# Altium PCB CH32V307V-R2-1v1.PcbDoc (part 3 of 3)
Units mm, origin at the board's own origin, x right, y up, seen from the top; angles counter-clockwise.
Board outline 80 x 115 mm, 2 copper layers (Top Layer, Bottom Layer); 122 components, 134 nets, 559 pads, 721 vias.
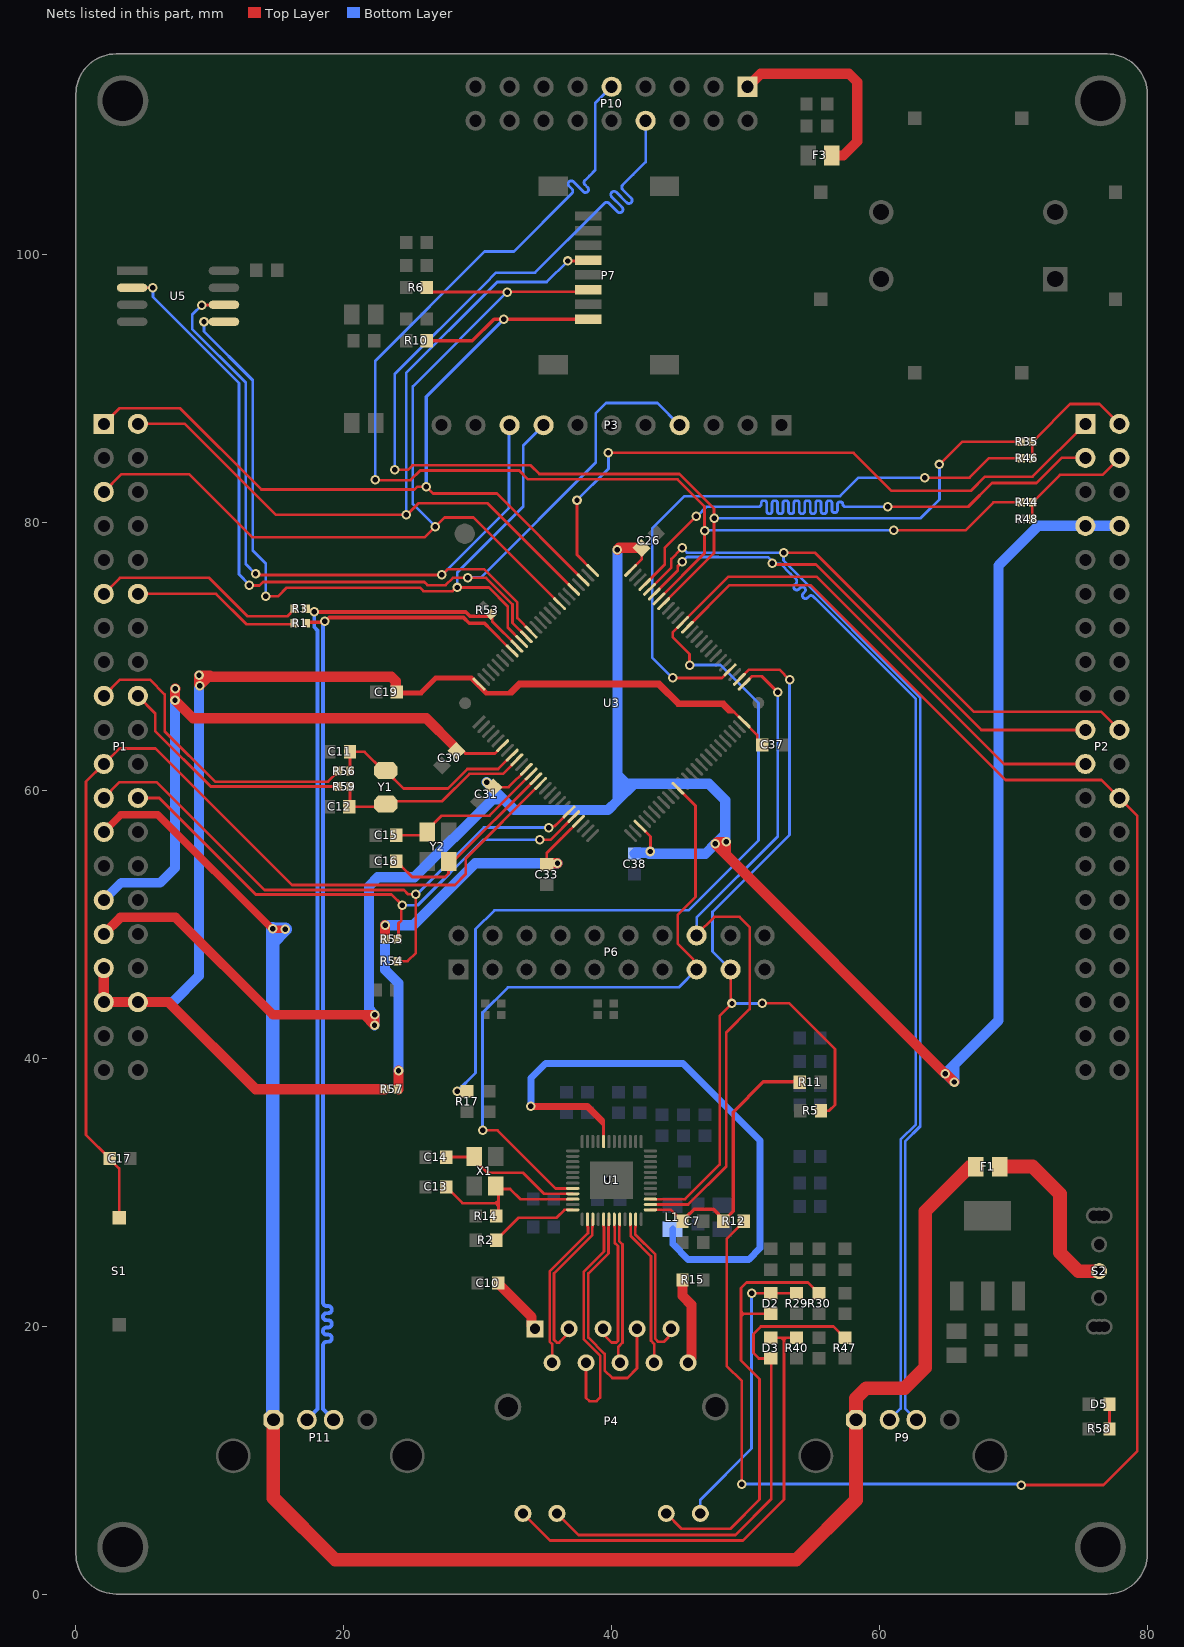
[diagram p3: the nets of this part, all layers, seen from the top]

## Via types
v1: diameter 0.711, hole 0.406, Top Layer to Bottom Layer, tented both sides, 507 vias
v2: diameter 0.61, hole 0.305, Top Layer to Bottom Layer, tented both sides, 214 vias

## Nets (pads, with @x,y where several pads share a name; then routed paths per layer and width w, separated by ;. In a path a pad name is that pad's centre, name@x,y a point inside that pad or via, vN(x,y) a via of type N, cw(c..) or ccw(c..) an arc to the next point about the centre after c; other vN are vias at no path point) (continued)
LED_green_n: D3.K P4.12 R47.1 | length 38.6
  Top Layer w0.203: P4.12@35.915,6.017 37.523,4.409 49.252,4.409 51.923,7.08 51.923,17.589 50.991,17.589 50.587,17.992 50.587,19.42 51.144,19.976 56.554,19.976 57.402,19.129 R47.1@57.427,19.129
LED_green_p: D3.A P4.11 R40.1 | length 36.1
  Top Layer w0.203: P4.11@33.375,6.017 35.395,3.997 49.814,3.997 52.873,7.056 52.873,18.932 ; D3.A@51.886,19.129 52.676,19.129 ; R40.1@53.817,19.129 53.027,19.129 ; 52.676,19.129 52.873,19.129 ; 52.676,19.129 52.873,18.932 ; 52.873,18.932 52.873,18.975 ; 52.873,18.975 52.873,19.129 ; 52.873,18.975 53.027,19.129 ; 52.873,19.129 53.027,19.129
LED_yellow_n: D2.K P4.13 R30.1 | length 33.9
  Top Layer w0.203: P4.13@44.085,6.017 45.228,4.875 48.869,4.875 51.049,7.055 51.049,16.059 49.658,17.451 49.658,20.716 ; D2.K@51.886,20.921 49.863,20.921 ; R30.1@55.495,22.461 55.47,22.461 54.67,23.261 50.079,23.261 49.658,22.84 49.658,21.127 ; 49.658,20.716 49.658,20.921 ; 49.658,20.716 49.863,20.921 ; 49.658,20.921 49.658,21.127 ; 49.658,20.921 49.863,20.921 ; 49.658,21.127 49.863,20.921
LED_yellow_p: D2.A P4.14 R29.2 | length 21.4
  Top Layer w0.203: v1(50.453,22.449) 51.392,22.449 51.404,22.461 R29.2@53.817,22.461
  Bottom Layer w0.203: P4.14@46.625,6.017 46.625,7.04 50.453,10.867 v1(50.453,22.449)
MAC_125M: P6.15 U1.44 U3.36 | length 49.8
  Top Layer w0.203: v1(30.368,34.627) 31.479,34.627 35.82,30.286 U1.44@37.1,30.286 ; U3.36@44.95,60.168 46.258,58.859 46.258,52.043 44.942,50.726 44.942,48.551 46.102,47.391 46.102,46.883 P6.15@46.35,46.634
  Bottom Layer w0.203: v1(30.368,34.627) 30.368,43.406 32.262,45.3 45.016,45.3 P6.15@46.35,46.634
MDI0_n: P4.3 U1.3 | length 12
  Top Layer w0.203: P4.3@36.823,19.807 36.823,19.519 36.075,18.771 35.925,18.771 35.793,18.903 35.704,18.992 35.704,23.949 38.565,26.811 38.565,27.411 38.597,27.442 38.597,27.983 U1.3@38.6,27.986
MDI0_p: P4.2 U1.2 | length 12
  Top Layer w0.203: P4.2@35.553,17.267 35.559,17.273 35.559,18.67 35.373,18.856 35.373,24.086 38.235,26.948 38.235,27.411 38.203,27.442 38.203,27.983 U1.2@38.2,27.986
MDI1_n: P4.7 U1.6 | length 18.3
  Top Layer w0.203: U1.6@39.8,27.986 39.797,27.983 39.797,27.442 39.765,27.411 39.765,25.436 38.26,23.931 38.26,19.152 39.479,17.932 39.479,16.701 40.052,16.129 41.173,16.129 41.903,16.859 P4.7@41.903,19.807
MDI1_p: P4.4 U1.5 | length 18.3
  Top Layer w0.203: P4.4@38.093,17.267 38.093,14.645 38.336,14.402 38.87,14.402 39.149,14.681 39.149,17.796 37.93,19.015 37.93,24.068 39.435,25.573 39.435,27.411 39.403,27.442 39.403,27.983 U1.5@39.4,27.986
MDI2_n: P4.6 U1.8 | length 11
  Top Layer w0.203: U1.8@40.6,27.986 40.597,27.983 40.597,27.442 40.565,27.411 40.565,26.356 40.813,26.108 40.813,18.768 40.499,18.454 40.499,17.402 P4.6@40.633,17.267
MDI2_p: P4.5 U1.7 | length 11
  Top Layer w0.203: P4.5@39.363,19.807 39.567,19.603 39.567,19.204 39.989,18.782 40.36,18.782 40.483,18.905 40.483,25.971 40.235,26.219 40.235,27.411 40.203,27.442 40.203,27.983 U1.7@40.2,27.986
MDI3_n: P4.9 U1.11 | length 11.5
  Top Layer w0.203: U1.11@41.8,27.986 41.797,27.983 41.797,27.442 41.765,27.411 41.765,26.852 43.264,25.353 43.264,19.052 43.48,18.836 43.902,18.836 44.239,19.173 44.239,19.603 P4.9@44.443,19.807
MDI3_p: P4.8 U1.10 | length 11.5
  Top Layer w0.203: U1.10@41.4,27.986 41.403,27.983 41.403,27.442 41.435,27.411 41.435,26.715 42.934,25.216 42.934,18.915 43.179,18.67 43.179,17.273 P4.8@43.173,17.267
NetC10_1: C10.1 P4.1 | length 4.5
  Top Layer w0.762: C10.1@31.526,23.212 31.526,23.187 34.029,20.684 34.029,20.061 P4.1@34.283,19.807
NetD5_K: D5.K R58.2 | length 1.8
  Top Layer w0.254: R58.2@77.178,12.329 D5.K@77.178,14.168
NetF1_2: F1.2 S2.1 | length 13.2
  Top Layer w1.016: F1.2@68.971,31.92 71.435,31.92 73.485,29.87 73.485,25.486 74.865,24.106 S2.1@76.403,24.106
NetF3_1: F3.1 P10.1 | length 15.6
  Top Layer w0.762: P10.1@50.16,112.547 51.125,113.512 57.724,113.512 58.335,112.901 58.335,108.457 57.297,107.419 F3.1@56.447,107.419
NetP2_2: P2.2 R35.1 R46.1 | length 9.5
  Top Layer w0.203: R46.1@71.416,84.811 R35.1@71.416,86.037 71.416,86.062 71.615,86.26 71.64,86.26 74.243,88.864 76.435,88.864 P2.2@77.919,87.38
NetP2_4: P2.4 R44.1 R48.1 | length 9.1
  Top Layer w0.203: R48.1@71.416,80.265 R44.1@71.416,81.518 71.416,81.543 71.615,81.741 71.64,81.741 73.468,83.569 76.648,83.569 P2.4@77.919,84.84
NetP4_10: P4.10 R15.1 | length 6.6
  Top Layer w0.762: R15.1@45.292,23.455 45.292,22.268 45.959,21.602 45.959,17.651 45.713,17.405 P4.10@45.713,17.267
NRST: C17.2 P1.21 S1.2 U3.14 | length 76.6
  Top Layer w0.203: S1.2@3.233,28.106 3.233,31.77 2.515,32.488 C17.2@2.515,32.513 2.515,32.538 0.762,34.291 0.762,60.661 P1.21@2.081,61.98 3.242,63.141 5.941,63.141 16.145,52.937 28.301,52.937 29.112,53.748 29.112,54.937 U3.14@34.697,60.522
PB6: P1.11 R3.2 | length 16.2
  Top Layer w0.203: P1.11@2.081,74.68 3.277,75.876 9.959,75.876 12.823,73.012 15.787,73.012 R3.2@16.336,73.562
PB7: P1.12 R1.2 | length 12.7
  Top Layer w0.203: P1.12@4.621,74.68 10.469,74.68 12.737,72.413 R1.2@16.336,72.413
PC14: P1.17 R56.2 | length 23.2
  Top Layer w0.203: P1.17@2.081,67.06 3.299,68.278 5.527,68.278 6.628,67.177 6.628,64.424 10.395,60.657 18.823,60.657 19.394,61.228 19.419,61.228 19.618,61.427 R56.2@19.618,61.452
PC15: P1.18 R59.2 | length 18.6
  Top Layer w0.203: P1.18@4.621,67.06 5.917,65.765 5.917,64.447 10.071,60.293 R59.2@19.618,60.293
PHY2_int: P2.21 R17.2 U3.64 | length 95.5
  Top Layer w0.203: v1(28.473,37.541) 28.73,37.541 28.847,37.425 29.205,37.783 R17.2@29.205,37.589 ; v1(45.822,69.367) 45.822,70.191 44.562,71.451 44.562,71.801 U3.64@45.303,72.542 48.729,75.968 55.306,75.968 69.294,61.98 P2.21@75.379,61.98
  Bottom Layer w0.203: v1(28.473,37.541) 29.837,38.905 29.837,49.643 31.246,51.052 45.734,51.052 50.961,56.279 50.961,66.533 48.127,69.367 v1(45.822,69.367)
PHY2_reset: P2.24 R12.2 U3.63 | length 140.7
  Top Layer w0.203: U3.63@45.657,72.189 48.801,75.333 54.855,75.333 69.41,60.777 76.582,60.777 P2.24@77.919,59.44 79.243,58.117 79.243,10.651 76.725,8.134 v1(70.582,8.134) ; v1(49.721,8.213) 49.721,15.908 48.592,17.038 48.592,26.524 49.875,27.808 R12.2@49.875,27.833
  Bottom Layer w0.203: v1(49.721,8.213) 70.502,8.213 v1(70.582,8.134)
PHYRSTB: C7.2 R11.1 R12.1 U1.13 | length 20.8
  Top Layer w0.178: U1.13@42.9,28.686 44.439,28.686 44.891,28.234 44.916,28.234 C7.2@45.292,27.858
  Top Layer w0.254: C7.2@45.292,27.858 45.63,28.196 46.173,28.738 47.608,28.738 48.424,27.921 48.424,27.946 48.673,28.196 48.698,28.196 49.08,28.577 49.08,35.989 51.333,38.242 54.035,38.242 R11.1@54.061,38.216
PVIN: F1.1 P1.25 P9.1 P11.1 | length 140.2
  Top Layer w0.559: P1.25@2.081,56.9 3.366,58.185 6.121,58.185 14.644,49.663 v1(14.685,49.663) 14.697,49.651 15.618,49.651 v1(15.629,49.639)
  Top Layer w1.016: P11.1@14.747,13.012 14.747,7.174 19.365,2.556 53.795,2.556 58.253,7.014 P9.1@58.253,13.012 58.253,14.614 59.015,15.377 61.887,15.377 63.42,16.91 63.42,28.58 66.743,31.903 F1.1@67.191,31.903
  Bottom Layer w1.016: P11.1@14.747,13.012 14.685,13.074 14.685,48.695 ; 14.685,48.695 v1(15.629,49.639) 14.709,49.639 v1(14.685,49.663) 14.685,48.695
REGOUT: L1.1 U1.32 | length 48.2
  Top Layer w0.203: 38.898,35.489 39.397,34.991 39.397,33.79 U1.32@39.4,33.786 39.4,35.21 ; 39.224,35.534 39.4,35.357 39.4,35.21 ; 39.243,35.367 39.4,35.21
  Top Layer w0.508: v1(33.978,36.408) 38.201,36.408 39.243,35.367
  Bottom Layer w0.508: v1(33.978,36.408) 33.978,38.523 35.077,39.622 45.322,39.622 51.088,33.857 51.088,25.824 50.243,24.98 45.715,24.98 44.571,26.123 L1.1@44.571,27.252
RGMII_MDC: P6.16 U1.14 U3.51 | length 54.2
  Top Layer w0.203: U1.14@42.9,29.086 45.718,29.086 48.561,31.929 48.561,41.939 50.31,43.689 50.31,49.797 49.545,50.562 47.68,50.562 46.35,49.232 P6.16@46.35,49.174 ; U3.51@49.899,67.946 49.906,67.946 50.49,68.53 51.21,68.53 v1(52.407,67.334)
  Bottom Layer w0.203: P6.16@46.35,49.174 46.35,50.515 52.407,56.572 v1(52.407,67.334)
RGMII_MDIO: P6.17 R5.2 U1.15 U3.52 | length 64.7
  Top Layer w0.203: U1.15@42.9,29.486 45.488,29.486 48.066,32.064 48.066,43.173 v1(48.989,44.096) 48.89,44.195 P6.17@48.89,46.634 ; U3.52@49.546,68.3 50.271,69.025 52.526,69.025 v1(53.288,68.263) ; v1(51.255,44.122) 53.243,44.122 56.682,40.684 56.682,36.527 56.241,36.086 R5.2@55.635,36.086
  Bottom Layer w0.203: P6.17@48.89,46.634 47.54,47.985 47.54,50.935 53.288,56.684 v1(53.288,68.263) ; v1(48.989,44.096) v1@51.255,44.096
RSET: R2.1 U1.48 | length 6.7
  Top Layer w0.203: R2.1@31.389,26.416 31.389,26.441 33.043,28.094 35.877,28.094 36.469,28.686 U1.48@37.1,28.686
SDIO_CLK: P1.2 P7.5 U3.80 | length 66.1
  Top Layer w0.203: P1.2@4.621,87.38 8.131,87.38 14.917,80.594 v1(24.663,80.594) 24.74,80.594 25.593,81.447 30.741,81.447 U3.80@37.172,75.017 ; v1(36.731,99.538) 38.231,99.538 38.272,99.579 P7.5@38.25,99.601
  Bottom Layer w0.203: v1(24.663,80.594) 24.663,91.041 24.663,91.16 30.901,97.398 31.464,97.961 35.154,97.961 v1(36.731,99.538)
SDIO_CMD: P1.5 P7.3 R6.1 U3.83 | length 73.2
  Top Layer w0.203: P1.5@2.081,82.3 3.398,83.617 8.453,83.617 13.172,78.899 26.043,78.899 v1(26.848,79.704) 27.524,80.381 29.687,80.381 U3.83@36.111,73.957 ; R6.1@26.192,97.549 26.524,97.217 v1(32.196,97.217) 32.228,97.249 38.098,97.249 P7.3@38.25,97.401
  Bottom Layer w0.203: v1(26.848,79.704) 25.158,81.393 25.158,90.178 v1(32.196,97.217)
SDIO_D2: P1.1 P7.1 R10.1 U3.78 | length 74.2
  Top Layer w0.203: P1.1@2.081,87.38 3.245,88.544 7.779,88.544 13.848,82.475 25.277,82.475 25.478,82.677 v1(26.162,82.677) 26.668,82.171 31.432,82.171 U3.78@37.87,75.733
  Top Layer w0.254: R10.1@26.192,93.583 29.602,93.583 31.219,95.201 36.775,95.201 ; v1(31.954,95.195) 36.769,95.195 36.775,95.201 ; P7.1@38.25,95.201 36.775,95.201
  Bottom Layer w0.254: v1(26.162,82.677) 26.162,89.404 v1(31.954,95.195)
SPI3_MISO: P3.4 U3.90 U5.2 | length 74.6
  Top Layer w0.203: U5.2@4.196,97.541 v1@5.751,97.542 ; v1(12.938,75.311) 13.709,75.311 13.963,75.566 26.013,75.566 26.247,75.331 27.603,75.331 28.149,75.878 v1(29.27,75.878) 30.626,75.878 32.603,73.901 32.603,72.515 U3.90@33.636,71.482
  Bottom Layer w0.203: v1(5.752,97.543) 5.752,96.856 12.173,90.435 12.173,76.148 12.938,75.383 v1(12.938,75.311) ; v1(29.27,75.878) 29.289,75.897 30.233,75.897 38.811,84.474 38.811,88.157 39.586,88.933 43.422,88.933 P3.4@45.08,87.274
SPI3_MOSI: P3.8 U3.91 U5.5 | length 60.9
  Top Layer w0.203: v1(9.564,95.017) 9.572,95.009 11.047,95.009 U5.5@11.054,95.001 ; v1(14.173,74.498) 15.097,74.498 15.743,75.144 25.692,75.144 25.952,74.884 28.13,74.884 28.405,75.159 30.842,75.159 32.247,73.754 32.247,72.164 U3.91@33.282,71.128
  Bottom Layer w0.203: v1(9.564,95.017) 9.564,94.27 13.204,90.631 13.204,77.929 14.173,76.96 v1(14.173,74.498) ; v1(28.473,75.159) 28.473,76.272 33.4,81.199 33.4,85.755 P3.8@34.92,87.274
SPI3_SCK: P3.9 U3.89 U5.6 | length 60.6
  Top Layer w0.203: v1(9.409,96.247) 9.421,96.259 11.042,96.259 U5.6@11.054,96.271 ; v1(13.411,76.175) 13.487,76.098 v1(27.33,76.098) ; v1@27.357,76.125 27.745,76.513 30.494,76.513 32.958,74.049 32.958,72.867 U3.89@33.99,71.835
  Bottom Layer w0.203: v1(9.409,96.247) 8.683,95.521 8.683,94.453 12.681,90.454 12.681,76.905 v1(13.411,76.175) ; v1(27.33,76.098) 32.339,81.107 32.339,87.234 P3.9@32.38,87.274
SWDCK: P2.1 U3.76 | length 49.3
  Top Layer w0.203: v1(37.416,81.681) 37.416,77.601 U3.76@38.586,76.431 ; v1(39.762,85.215) 58.055,85.215 60.892,82.378 66.82,82.378 67.871,83.429 71.428,83.429 P2.1@75.379,87.38
  Bottom Layer w0.203: v1@37.275,81.539 39.762,84.026 v1(39.762,85.215)
SWDIO: P2.3 U3.72 | length 49.3
  Top Layer w0.203: U3.72@42.475,75.371 43.962,76.858 43.962,78.12 v1(46.305,80.464) ; v1(60.634,81.185) 66.631,81.185 68.398,82.952 71.714,82.952 73.602,84.84 P2.3@75.379,84.84
  Bottom Layer w0.203: v1(46.305,80.464) 46.367,80.464 47.088,81.185 50.887,81.185 50.989,81.185 ccw(c50.989,81.368) 51.172,81.368 51.172,81.461 cw(c51.355,81.461) 51.355,81.644 51.395,81.644 cw(c51.395,81.461) 51.578,81.461 51.578,80.849 ccw(c51.761,80.849) 51.761,80.666 51.802,80.666 ccw(c51.802,80.849) 51.985,80.849 51.985,81.461 cw(c52.167,81.461) 52.167,81.644 52.208,81.644 cw(c52.208,81.461) 52.391,81.461 52.391,80.849 ccw(c52.574,80.849) 52.574,80.666 52.615,80.666 ccw(c52.615,80.849) 52.797,80.849 52.797,81.461 cw(c52.98,81.461) 52.98,81.644 53.021,81.644 cw(c53.021,81.461) 53.204,81.461 53.204,80.849 ccw(c53.387,80.849) 53.387,80.666 53.427,80.666 ccw(c53.427,80.849) 53.61,80.849 53.61,81.461 cw(c53.793,81.461) 53.793,81.644 53.834,81.644 cw(c53.834,81.461) 54.017,81.461 54.017,80.849 ccw(c54.199,80.849) 54.199,80.666 54.24,80.666 ccw(c54.24,80.849) 54.423,80.849 54.423,81.461 cw(c54.606,81.461) 54.606,81.644 54.647,81.644 cw(c54.647,81.461) 54.829,81.461 54.829,80.849 ccw(c55.012,80.849) 55.012,80.666 55.053,80.666 ccw(c55.053,80.849) 55.236,80.849 55.236,81.461 cw(c55.419,81.461) 55.419,81.644 55.459,81.644 cw(c55.459,81.461) 55.642,81.461 55.642,80.849 ccw(c55.825,80.849) 55.825,80.666 55.866,80.666 ccw(c55.866,80.849) 56.049,80.849 56.049,81.461 cw(c56.231,81.461) 56.231,81.644 56.272,81.644 cw(c56.272,81.461) 56.455,81.461 56.455,80.932 ccw(c56.638,80.932) 56.638,80.749 56.679,80.749 ccw(c56.679,80.932) 56.861,80.932 56.861,81.368 cw(c57.044,81.368) 57.044,81.55 57.085,81.55 cw(c57.085,81.368) 57.268,81.368 ccw(c57.451,81.368) 57.451,81.185 59.977,81.185 v1(60.634,81.185)
U1_RX/DVP_D1: P10.9 R44.2 U3.69 | length 99.2
  Top Layer w0.203: v1(22.352,83.21) 22.391,83.172 24.994,83.172 25.71,83.887 33.106,83.887 33.758,83.234 44.913,83.234 46.94,81.207 v1(46.94,79.407) 46.94,77.715 U3.69@43.536,74.31 ; v1(61.051,79.425) 66.424,79.425 68.517,81.518 R44.2@70.566,81.518
  Bottom Layer w0.203: v1(22.352,83.21) 22.352,92.084 30.519,100.252 32.697,100.252 36.965,104.52 37.037,104.592 ccw(c36.875,104.753) 37.037,104.915 36.822,105.13 cw(c36.983,105.292) 36.822,105.453 cw(c36.983,105.292) 37.145,105.453 37.885,104.713 ccw(c38.047,104.875) 38.209,105.036 38.007,105.238 cw(c38.168,105.4) 38.007,105.562 38.344,105.899 38.779,106.334 38.779,111.327 P10.9@40,112.547 ; v1(46.94,79.407) 46.967,79.434 v1@61.047,79.434
U1_TX/DVP_D0: P10.8 R35.2 U3.68 | length 101.7
  Top Layer w0.203: v1(23.81,83.94) 24.792,83.94 25.134,84.282 33.962,84.282 34.605,83.639 45.075,83.639 47.652,81.062 v1(47.652,80.336) 47.652,77.72 U3.68@43.889,73.957 ; v1(64.479,84.342) 66.174,86.037 R35.2@70.566,86.037 70.389,86.214 R35.2@70.35,86.174
  Bottom Layer w0.203: v1(23.81,83.94) 23.81,91.096 30.502,97.788 31.383,98.669 34.281,98.669 39.05,103.437 39.463,103.85 cw(c39.633,103.679) 39.804,103.85 40.438,103.216 ccw(c40.609,103.386) 40.78,103.557 40.009,104.328 cw(c40.18,104.498) 40.009,104.669 cw(c40.18,104.498) 40.35,104.669 41.121,103.898 ccw(c41.292,104.069) 41.462,104.24 40.828,104.874 cw(c40.998,105.044) 40.828,105.215 41.613,106 42.54,106.927 P10.8@42.54,110.007 ; v1(47.652,80.336) 63.084,80.336 64.479,81.731 v1(64.479,84.342)
UART1_TX_2: R46.2 U3.54 | length 46
  Top Layer w0.203: v1(44.552,68.402) 48.234,68.402 U3.54@48.839,69.007 ; v1(63.367,83.356) 66.718,83.356 68.173,84.811 R46.2@70.566,84.811
  Bottom Layer w0.203: v1(44.552,68.402) 43.026,69.928 43.026,79.558 45.442,81.975 57.058,81.975 58.439,83.356 v1(63.367,83.356)
USB1D_n: P2.19 P9.2 U3.70 | length 110.1
  Top Layer w0.203: U3.70@43.182,74.664 44.938,76.42 44.938,76.745 45.268,77.075 v1(45.272,77.075) ; v1(52.003,76.951) 52.086,76.868 55.259,76.868 67.607,64.52 P2.19@75.379,64.52
  Bottom Layer w0.203: v1(45.272,77.075) 45.625,77.428 47.956,77.428 47.961,77.422 51.669,77.422 v1@52.071,77.02 ; v1(52.003,76.951) 52.015,76.939 52.607,76.939 53.368,76.179 53.763,75.784 cw(c53.601,75.622) 53.763,75.46 53.662,75.36 ccw(c53.824,75.198) 53.985,75.036 54.086,75.137 cw(c54.248,74.975) 54.409,75.137 cw(c54.248,74.975) 54.409,74.814 54.309,74.713 ccw(c54.47,74.551) 54.309,74.39 ccw(c54.47,74.551) 54.632,74.39 54.733,74.491 cw(c54.894,74.329) 55.056,74.491 55.441,74.105 62.719,66.828 62.719,35.068 61.588,33.937 61.588,13.847 P9.2@60.753,13.012
USB1D_p: P2.20 P9.3 U3.71 | length 112.1
  Top Layer w0.203: U3.71@42.828,75.017 44.463,76.652 44.463,77.295 45.195,78.026 v1@45.236,78.026 ; v1(52.853,77.752) 55.197,77.752 67.076,65.873 76.566,65.873 P2.20@77.919,64.52
  Bottom Layer w0.203: v1(45.272,78.111) 45.625,77.758 48.092,77.758 48.098,77.752 v1(52.853,77.752) 52.841,77.74 52.841,77.172 63.049,66.964 63.049,34.931 61.918,33.8 61.918,13.847 P9.3@62.753,13.012
USB2D_n: P11.2 R3.1 R53.1 U3.92 | length 78.3
  Top Layer w0.203: 30.594,72.967 R53.1@31.064,72.967 ; R53.1@31.087,73.024 31.087,72.617 U3.92@32.929,70.775
  Top Layer w0.279: R3.1@17.186,73.486 R3.1@17.259,73.412 ; R3.1@17.264,73.408 R3.1@17.259,73.412 ; R53.1@31.064,72.967 31.026,73.006 29.432,73.006 29.107,73.331 17.807,73.331 v1(17.805,73.33) 17.723,73.412 R3.1@17.259,73.412
  Bottom Layer w0.279: P11.2@17.247,13.012 18.044,13.809 18.044,71.951 17.805,72.189 v1(17.805,73.33)
USB2D_p: P11.3 R1.1 U3.93 | length 79.3
  Top Layer w0.203: 30.488,72.509 30.507,72.49 ; 30.696,72.3 U3.93@32.575,70.421
  Top Layer w0.279: R1.1@17.186,72.489 17.255,72.558 18.506,72.558 v1(18.576,72.628) ; v1@18.459,72.628 v1(18.576,72.628) ; 30.696,72.3 30.507,72.49 29.374,72.49 28.939,72.925 18.914,72.925 18.617,72.628 v1(18.576,72.628)
  Bottom Layer w0.279: v1(18.576,72.628) 18.493,72.545 18.493,72.332 18.45,72.289 18.45,71.08 18.45,22.67 18.45,21.772 ccw(c18.717,21.772) 18.717,21.505 18.839,21.505 cw(c18.839,21.239) 18.839,20.972 18.717,20.972 ccw(c18.717,20.705) 18.717,20.438 18.839,20.438 cw(c18.839,20.172) 18.839,19.905 18.717,19.905 ccw(c18.717,19.638) 18.717,19.372 18.839,19.372 cw(c18.839,19.105) 18.839,18.838 18.717,18.838 ccw(c18.717,18.572) 18.45,18.572 18.45,17.898 18.45,13.809 P11.3@19.247,13.012
VBAT: C30.2 P1.29 U3.6 | length 46.5
  Top Layer w0.203: C30.2@28.423,62.965 28.886,62.965 29.082,62.769 31.287,62.769 U3.6@31.868,63.35
  Top Layer w0.762: v1(7.417,67.6) 7.4,67.582 v1(7.4,66.734) 8.743,65.39 26.164,65.39 C30.2@28.193,63.362
  Bottom Layer w0.711: P1.29@2.081,51.82 3.389,53.128 6.316,53.128 7.4,54.212 v1(7.4,66.734) v1@7.4,67.6
VDD: C26.2 C31.1 C38.2 P1.31 P2.7 P2.8 U3.11 U3.28 U3.75 | length 194.2
  Top Layer w0.203: v1(30.666,60.609) 31.03,60.246 C31.1@31.19,60.246 31.208,60.228 31.722,60.228 31.74,60.246 32.299,60.246 U3.11@33.636,61.582 ; U3.75@41.414,76.431 42.244,77.261 42.244,77.554 42.262,77.571 42.262,78.085 C26.2@42.244,78.103 ; U3.28@42.121,57.34 42.904,56.557 42.904,55.468 v1(42.879,55.443)
  Top Layer w0.711: P1.31@2.081,49.28 3.328,50.527 7.445,50.527 14.701,43.27 21.492,43.27 ; v1(47.748,56.012) 47.906,56.171 v1(48.548,56.171) 48.548,55.211 49.009,54.75 ; 21.492,43.27 v1(22.297,42.465) 22.303,42.472 v1(22.303,43.27) 21.492,43.27
  Top Layer w0.762: v1(40.434,77.977) 40.577,78.121 42.107,78.121 42.143,78.085 C26.2@42.262,78.085 ; v1(47.748,56.012) 48.548,55.211 64.899,38.86 v1(64.921,38.86) 64.966,38.86 v1(65.595,38.231)
  Bottom Layer w0.762: v1(22.297,42.465) v1@22.297,43.277 ; v1(22.303,43.27) v1@22.297,43.277 ; v1(30.666,60.609) 31.091,60.184 ; 40.434,63.044 40.434,61.171 40.437,61.168 ; v1(40.434,77.977) 40.434,63.912 40.437,63.909 40.437,61.168 ; C38.2@41.718,55.272 41.802,55.356 42.791,55.356 v1(42.879,55.443) ; v1@42.791,55.272 47.008,55.272 v1(47.748,56.012) v1@47.906,56.171 ; P2.8@77.919,79.76 P2.7@75.379,79.76 71.852,79.76 68.898,76.806 68.898,42.837 65.595,39.534 ; v1@22.297,43.277 21.883,43.691 21.883,52.857 22.542,53.517 25.274,53.517 31.077,59.32 ; 31.077,59.32 31.937,59.32 31.946,59.329 ; 31.077,59.32 31.516,59.759 ; 31.077,59.32 31.077,60.17 31.091,60.184 ; 31.091,60.184 31.516,59.759 ; 31.516,59.759 31.946,59.329 ; 31.946,59.329 32.722,58.553 39.74,58.553 40.437,59.25 ; 40.437,59.25 41.687,60.5 ; 40.437,59.25 40.437,60.5 ; 40.437,60.5 41.105,60.5 ; 40.437,60.5 40.437,61.168 ; 40.437,61.168 41.105,60.5 ; 41.105,60.5 41.687,60.5 ; 41.687,60.5 47.264,60.5 48.487,59.277 48.487,56.752 ; v1@47.906,56.171 48.487,56.752 ; v1@47.906,56.171 v1(48.548,56.171) 48.487,56.231 48.487,56.752 ; 65.595,39.534 v1(65.595,38.231) 64.966,38.86 v1(64.921,38.86) 65.595,39.534
VDDA: C33.1 R55.1 R57.2 U3.22 | length 35
  Top Layer w0.203: C33.1@35.157,54.494 35.157,55.325 U3.22@37.525,57.693 37.518,57.693 36.415,56.59
  Top Layer w0.762: R55.1@23.083,48.975 v1(23.083,49.93) ; R57.2@24.089,37.695 v1(24.089,39.08) ; C33.1@35.157,54.494 35.228,54.564 v1(35.959,54.564)
  Bottom Layer w0.762: v1(24.089,39.08) 24.089,45.608 23.083,46.615 v1(23.083,49.93) 25.182,49.93 29.817,54.564 v1(35.959,54.564)
VIO: C19.1 C37.2 P1.33 P1.35 P1.36 R57.1 U3.50 U3.100 | length 150.2
  Top Layer w0.178: U3.50@49.899,65.118 50.868,64.149 50.868,63.779 C37.2@51.244,63.403
  Top Layer w0.203: U3.50@49.899,65.118 49.153,65.864 ; 25.549,67.21 25.82,67.21 26.938,68.328 29.458,68.328 30.471,67.316 ; 25.549,67.21 24.094,67.21 C19.1@23.956,67.348 23.987,67.379 25.718,67.379 ; 25.549,67.21 25.718,67.379 ; 25.718,67.379 26.837,68.499 29.548,68.499 U3.100@30.101,67.946 30.731,67.316 ; 30.471,67.316 30.586,67.201 32.421,67.201 ; 30.471,67.316 30.731,67.316 ; 30.731,67.316 32.27,67.316 33.06,68.106 43.599,68.106 45.094,66.611 48.406,66.611 49.153,65.864 ; 32.421,67.201 32.608,67.201 33.212,67.805 43.438,67.805 44.913,66.33 48.222,66.33 48.687,65.864 48.907,65.864 ; 32.421,67.201 33.143,67.923 43.528,67.923 44.993,66.458 48.313,66.458 48.907,65.864 ; 48.907,65.864 49.153,65.864
  Top Layer w0.762: P1.33@2.081,46.74 P1.35@2.081,44.2 P1.36@4.621,44.2 6.914,44.2 13.423,37.691 R57.1@23.073,37.691 ; C19.1@23.956,67.378 23.877,67.457 23.877,68.159 23.542,68.493 9.891,68.493 ; 9.891,68.493 9.26,67.863 9.193,67.93 v1(9.193,68.594) 9.991,68.594 9.891,68.493
  Bottom Layer w0.762: P1.35@2.081,44.2 P1.36@4.621,44.2 7.232,44.2 9.193,46.161 v1(9.193,68.594)
  other v1: 9.26,67.837
VREF+: P1.24 R55.2 U3.21 | length 41.3
  Top Layer w0.203: P1.24@4.621,59.44 6.223,59.44 13.43,52.234 23.572,52.234 v1(24.378,51.428) 24.3,51.351 24.3,50.303 24.084,50.086 24.084,48.958 R55.2@24.017,48.891 ; v1(34.634,56.317) 35.442,56.317 U3.21@37.172,58.047
  Bottom Layer w0.203: v1(24.378,51.428) 25.523,51.428 30.412,56.317 v1(34.634,56.317)
VREF-: P1.23 R54.2 U3.20 | length 47.3
  Top Layer w0.203: P1.23@2.081,59.44 3.264,60.623 6.016,60.623 14.075,52.564 24.484,52.564 24.795,52.253 v1(25.384,52.253) 25.384,47.868 24.775,47.26 R54.2@23.937,47.26 ; v1(35.3,57.232) 35.398,57.329 35.747,57.329 36.07,57.652 ; 36.07,57.652 U3.20@36.818,58.4
  Bottom Layer w0.203: v1(25.384,52.253) 25.485,52.253 30.464,57.232 35.25,57.232 v1@35.275,57.258
X32KI: C11.2 R56.1 U3.8 Y1.1 | length 15.7
  Top Layer w0.203: R56.1@20.468,61.452 C11.2@20.468,62.889 21.558,62.889 22.973,61.474 Y1.1@23.137,61.474 24.468,60.143 27.77,60.143 29.226,61.6 31.532,61.6 U3.8@32.575,62.643
X32KO: C12.2 R59.1 U3.9 Y1.2 | length 15.6
  Top Layer w0.203: R59.1@20.468,60.293 20.468,58.826 C12.2@20.427,58.786 23.021,58.786 Y1.2@23.137,58.67 ; Y1.2@22.962,58.945 23.214,59.196 27.326,59.196 29.374,61.244 31.884,61.244 U3.9@32.929,62.289
XI: C15.2 U3.12 Y2.1 | length 12.2
  Top Layer w0.203: C15.2@23.811,56.78 C15.2@23.937,56.655 25.979,56.655 Y2.1@26.227,56.903 26.227,57.028 27.316,58.117 30.878,58.117 U3.12@33.99,61.229
XO: C16.2 U3.13 Y2.3 | length 14.5
  Top Layer w0.203: C16.2@23.937,54.719 23.937,54.694 24.3,54.33 24.325,54.33 25.115,53.541 27.56,53.541 27.827,53.807 Y2.3@27.827,54.703 28.171,54.703 U3.13@34.343,60.875
XTAL1: C13.2 R14.1 U1.46 X1.3 | length 13
  Top Layer w0.203: C13.2@27.643,30.404 27.643,30.379 28.006,30.015 28.031,30.015 28.86,29.187 31.321,29.187 ; R14.1@31.496,28.265 31.55,28.319 31.55,28.958 ; 31.539,29.187 31.343,29.187 ; X1.3@31.55,30.339 X1.3@31.55,30.239 ; U1.46@37.1,29.486 33.18,29.486 32.428,30.239 X1.3@31.55,30.239 ; 31.321,29.187 31.343,29.187 ; 31.321,29.187 31.55,28.958 ; 31.343,29.187 31.55,29.393 ; 31.55,28.958 31.55,29.393 ; 31.55,29.393 X1.3@31.55,30.239
XTAL2: C14.2 U1.45 X1.1 | length 10.7
  Top Layer w0.203: C14.2@27.672,32.525 27.786,32.639 29.649,32.639 29.649,32.539 30.733,31.456 33.384,31.456 34.953,29.886 U1.45@37.1,29.886
pads on no net: ?.0 S2.0 S2.3 S7.2 S7.4 U1.33 U1.38 U1.39 U1.40 U1.41 U1.42 U1.43 U3.0 U3.73 U4.2@68.081,28.254

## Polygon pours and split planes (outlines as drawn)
GND on Bottom Layer "GND" (hatched 90Degree grid 0.203 track 0.203, remove dead copper, pour order 1): -0.212,-0.498 -0.212,115.574 0.092,115.878 0.244,115.726 80.262,115.726 80.262,-0.345
GND on Top Layer "GND" (hatched 90Degree grid 0.203 track 0.203, remove dead copper, pour order 0): 0.092,115.27 80.262,115.27 80.414,115.117 80.414,-0.498 0.092,-0.498 -0.06,-0.345

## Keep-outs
Keep-Out Layer:
  lines w0.254: 0,3 ccw(c3,3) 3,0 77,0 ccw(c77,3) 80,3 80,112 ccw(c77,112) 77,115 3,115 ccw(c3,112) 0,112 0,3

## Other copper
Top Layer:
  pour cut-out: 35.457,28.844 43.851,28.844 46.743,25.952 46.743,16.736 43.12,13.113 35.608,13.113 33.11,15.611 33.11,25.587

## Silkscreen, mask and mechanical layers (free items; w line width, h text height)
Top Overlay:
  region: 74.634,90.057 76.07,90.057 75.346,88.949
  region: 60.182,90.057 61.619,90.057 60.895,88.949
  region: 7.321,90.057 8.757,90.057 8.033,88.949
  region: 1.336,90.057 2.772,90.057 2.049,88.949
  lines w0.152: 10.93,37.537 10.93,88.16 ; 63.281,79.041 63.281,88.282 ; 69.712,38.662 69.712,77.746
  text "CH32V307V-R2-1v1" at 4.438,104.871 h1.02
  text "SWCK" at 59.07,87.055 h0.89
  text "TXD" at 64.245,87.055 h0.89
  text "PC10" at 6.744,86.956 h0.89
  text "PC12" at 12.257,86.956 h0.89
  text "GND" at 26.844,85.637 h0.89 r270
  text "3V3" at 29.383,85.637 h0.89 r270
  text "SPI3_SCK" at 32.22,85.637 h0.89 r270
  text "SPI3_MOSI" at 34.759,85.637 h0.89 r270
  text "PA15" at 37.003,85.637 h0.89 r270
  text "PE2" at 39.543,85.637 h0.89 r270
  text "PE3" at 42.083,85.637 h0.89 r270
  text "SPI3_MISO" at 44.919,85.637 h0.89 r270
  text "PE4" at 47.162,85.637 h0.89 r270
  text "PE5" at 49.702,85.637 h0.89 r270
  text "PE6" at 52.242,85.637 h0.89 r270
  text "SWIO" at 59.683,84.524 h0.89
  text "RXD" at 64.152,84.524 h0.89
  text "PD0" at 7.117,84.411 h0.89
  text "PD1" at 12.82,84.411 h0.89
  text "GND" at 60.094,81.993 h0.89
  text "GND" at 64.059,81.993 h0.89
  text "PD2" at 7.117,81.866 h0.89
  text "PD3" at 12.629,81.866 h0.89
  text "VDD" at 60.187,79.461 h0.89
  text "VDD" at 64.152,79.461 h0.89
  text "PD4" at 7.095,79.321 h0.89
  text "PD5" at 12.629,79.321 h0.89
  text "5V" at 67.134,76.81 h0.89
  text "5V" at 71.486,76.81 h0.89
  text "PD6" at 7.138,76.776 h0.89
  text "PD7" at 12.629,76.776 h0.89
  text "GND" at 66.334,74.273 h0.89
  text "GND" at 70.686,74.273 h0.89
  text "PB6" at 7.138,74.231 h0.89
  text "PB7" at 12.629,74.231 h0.89
  text "GND" at 66.334,71.735 h0.89
  text "GND" at 70.686,71.735 h0.89
  text "PE0" at 7.163,71.686 h0.89
  text "PE1" at 12.866,71.686 h0.89
  text "GND" at 66.334,69.198 h0.89
  text "GND" at 70.686,69.198 h0.89
  text "GND" at 7.07,69.077 h0.89
  text "GND" at 12.582,69.077 h0.89
  text "GND" at 66.334,66.66 h0.89
  text "GND" at 70.686,66.66 h0.89
  text "PC14" at 6.723,66.545 h0.89
  text "PC15" at 12.257,66.545 h0.89
  text "PA11" at 66.063,64.081 h0.89
  text "PA12" at 70.603,64.081 h0.89
  text "GND" at 7.07,64.013 h0.89
  text "GND" at 12.582,64.013 h0.89
  text "PC7" at 66.334,61.539 h0.89
  text "GND" at 70.686,61.539 h0.89
  text "NRST" at 6.698,61.481 h0.89
  text "GND" at 12.582,61.481 h0.89
  text "PD15" at 65.776,58.998 h0.89
  text "PC6" at 70.603,58.998 h0.89
  text "VREF-" at 6.357,58.948 h0.89
  text "VREF+" at 11.869,58.948 h0.89
  text "PD13" at 65.776,56.456 h0.89
  text "PD14" at 70.603,56.456 h0.89
  text "PVIN" at 7.023,56.416 h0.89
  text "GND" at 12.582,56.416 h0.89
  text "PD11" at 66.156,53.915 h0.89
  text "PD12" at 70.603,53.915 h0.89
  text "GND" at 7.07,53.884 h0.89
  text "GND" at 12.582,53.884 h0.89
  text "PB12" at 45.91,53.814 h0.89 r270
  text "PC4" at 40.851,53.297 h0.89 r270
  text "GND" at 28.1,53.255 h0.89 r270
  text "PC3" at 33.111,53.255 h0.89 r270
  text "PA3" at 38.321,53.255 h0.89 r270
  text "PA8" at 48.44,53.255 h0.89 r270
  text "GND" at 50.97,53.255 h0.89 r270
  text "PB0" at 43.381,53.162 h0.89 r270
  text "PC1" at 30.705,52.874 h0.89 r270
  text "PA1" at 36.109,52.874 h0.89 r270
  text "PD9" at 66.47,51.374 h0.89
  text "PD10" at 70.603,51.374 h0.89
  text "VBAT" at 6.674,51.352 h0.89
  text "3V3" at 12.629,51.352 h0.89
  text "VDD" at 7.117,48.819 h0.89
  text "3V3" at 12.629,48.819 h0.89
  text "PE15" at 65.869,48.832 h0.89
  text "PD8" at 70.603,48.832 h0.89
  text "VIO" at 7.377,46.287 h0.89
  text "3V3" at 12.629,46.287 h0.89
  text "PE13" at 65.869,46.291 h0.89
  text "PE14" at 70.603,46.291 h0.89
  text "GND" at 28.18,44.945 h0.89 r270
  text "PC2" at 33.238,44.945 h0.89 r270
  text "PA0" at 35.902,44.945 h0.89 r270
  text "PA7" at 41.084,44.945 h0.89 r270
  text "PC5" at 43.395,44.945 h0.89 r270
  text "PB1" at 45.638,44.945 h0.89 r270
  text "PB13" at 48.356,44.945 h0.89 r270
  text "GND" at 51.157,44.945 h0.89 r270
  text "VIO" at 7.377,43.755 h0.89
  text "VIO" at 12.889,43.755 h0.89
  text "PE11" at 66.25,43.75 h0.89
  text "PE12" at 70.603,43.75 h0.89
  text "BOOT0" at 6.279,41.222 h0.89
  text "BOOT1" at 11.981,41.222 h0.89
  text "PE9" at 66.563,41.208 h0.89
  text "PE10" at 70.603,41.208 h0.89
  text "GND" at 7.07,38.69 h0.89
  text "GND" at 12.582,38.69 h0.89
  text "PE7" at 66.52,38.667 h0.89
  text "PE8" at 70.603,38.667 h0.89
  text "RST" at 5.845,25.353 h0.89 r270
  text "OFF" at 73.442,24.656 h0.89 r90
  text "ON" at 73.442,21.08 h0.89 r90
  text "HS" at 16.557,15.806 h2.29
  text "FS" at 60.324,15.579 h2.29
Bottom Overlay:
  region: 27.001,102.407 27.001,100.971 28.109,101.695
  region: 27.001,110.642 27.001,109.206 28.109,109.929
  lines w0.152: 27.815,103.588 51.712,103.588
  lines w0.203: 20.627,65.857 59.171,65.857 ; 20.627,70.539 59.171,70.539 ; 20.627,75.22 59.171,75.22 ; 34.026,61.351 34.026,77.768 ; 47.426,61.351 47.426,77.768 ; 20.627,61.176 59.171,61.176 59.171,77.768 20.627,77.768 20.627,61.176
  text "HSYNC" at 45.631,108.348 h0.89 r90
  text "VSYNC" at 48.175,108.301 h0.89 r90
  text "RESET" at 43.086,108.026 h0.89 r90
  text "GND" at 30.362,106.723 h0.89 r90
  text "3V3" at 50.72,106.629 h0.89 r90
  text "D7" at 32.907,105.838 h0.89 r90
  text "D5" at 35.452,105.838 h0.89 r90
  text "D3" at 37.996,105.838 h0.89 r90
  text "D1" at 40.541,105.457 h0.89 r90
  text "PWDN" at 30.362,102.967 h0.89 r90
  text "PCLK" at 32.907,102.967 h0.89 r90
  text "D6" at 35.452,102.967 h0.89 r90
  text "D4" at 37.996,102.967 h0.89 r90
  text "D2" at 40.541,102.967 h0.89 r90
  text "D0" at 43.086,102.967 h0.89 r90
  text "I2C2_SDA" at 45.631,102.967 h0.89 r90
  text "I2C2_SCL" at 48.175,102.967 h0.89 r90
  text "GND" at 50.72,102.967 h0.89 r90
  text "第二用法" at 30.933,75.822 h2.03
  text "默认" at 42.6,75.824 h2.03
  text "DVP_D5" at 30.799,73.002 h2.03
  text "USBHS_n" at 44.986,72.27 h2.03
  text "PB6" at 54.882,72.287 h2.03
  text "(需要焊接R53)" at 33.181,70.895 h2.03
  text "PB15" at 29.537,68.772 h2.03
  text "PA9" at 42.529,68.772 h2.03
  text "USART1_TX" at 58.449,67.165 h2.03
  text "(需要焊接R46)" at 33.181,66.328 h2.03
  text "(默认焊接R35)" at 46.691,66.328 h2.03
  text "PA8" at 29.018,64.019 h2.03
  text "PA10" at 43.032,64.019 h2.03
  text "USART1_RX" at 58.549,62.604 h2.03
  text "(需要焊接R48)" at 33.178,61.643 h2.03
  text "(默认焊接R44)" at 46.691,61.643 h2.03
  text "PC0" at 31.602,45.164 h0.89 r90
  text "PA2" at 39.184,45.164 h0.89 r90
Top Solder:
  drawing of 3656 lines, arcs and shapes, not listed
  text "http://wch.cn" at 9.587,19.849 h2.5
Mechanical 1:
  lines w0.254: 77,0 ccw(c77,3) 80,3 ; 77,115 cw(c77,112) 80,112 ; 77.001,0 3,0 cw(c3,3) 0,3 0,112 cw(c3,112) 3,115 77.007,115 ; 80,2.999 80,112.007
